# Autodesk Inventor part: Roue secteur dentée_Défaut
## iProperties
Shininess: 64.0
Length Units: 11269
Angle Units: 11279
Time Units: 11290
Mass Units: 11283
Length Display Precision: 3
Angle Display Precision: 2
Compacted: True
Part Number: Roue secteur dentée_Défaut
Document SubType Name: Modeling
Created: 2006-01
Material: Par défaut
Designer: Fricot
Density: 0.0
Volumn: 0.0
Area: 0.0
PropertySet Name: Model Information
Control State: 0
Master: False
Checked Out: False
Author: Fricot
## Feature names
1. Base1
